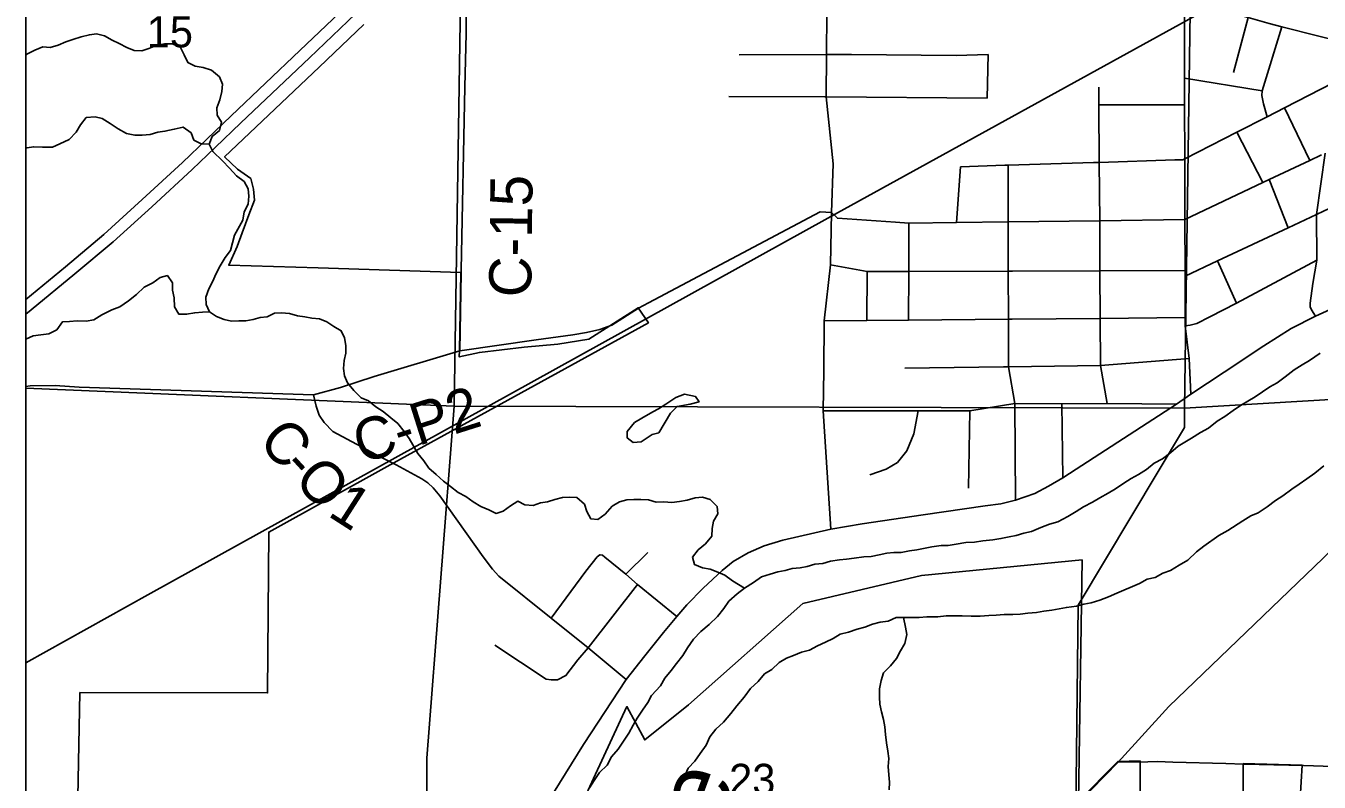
# Model space of a CAD drawing. Extents: x -6.2 to 37.4, y 0.2 to 22.2.
# Drawn here: x 1.681 to 2.552, y 16.626 to 17.135 of the extents above; entities that cross this region are included whole.
import ezdxf

# ---------------------------------------------------------------- set-up
doc = ezdxf.new("R2010")
doc.units = 0
for name, color, linetype in [('GM_X_City_Street', 7, 'Continuous'), ('GM_X_Corporation', 7, 'Continuous'), ('GM_X_County_Road', 7, 'Continuous'), ('GM_X_County_Road_Text', 7, 'Continuous'), ('GM_X_Major_River', 7, 'Continuous'), ('GM_X_Major_River_Text', 7, 'Continuous'), ('GM_X_Minor_Lake', 7, 'Continuous'), ('GM_X_Minor_River', 7, 'Continuous'), ('GM_X_Rail_Line', 7, 'Continuous'), ('GM_X_Section', 7, 'Continuous'), ('GM_X_Section_Text', 7, 'Continuous'), ('GM_X_Township_Road', 7, 'Continuous'), ('GM_X_US_Route', 7, 'Continuous'), ('GM_X_US_Shield', 7, 'Continuous'), ('SH_Cut_Line', 7, 'Continuous'), ('SH_Data', 7, 'Continuous')]:
    doc.layers.add(name, color=color, linetype=linetype)

msp = doc.modelspace()

# ---------------------------------------------------------------- linework, layer by layer
at = {"layer": 'GM_X_City_Street'}
for p, q in [((2.49427, 17.10375), (2.50408, 17.14076)), ((2.32831, 17.08654), (2.32914, 17.11596)), ((2.46132, 17.09991), (2.51363, 17.0913)), ((2.40366, 17.08196), (2.46137, 17.08188)), ((2.54559, 17.0446), (2.52864, 17.07998)), ((2.51401, 17.02959), (2.4965, 17.06358)), ((2.30763, 17.00267), (2.31032, 17.0403)), ((2.531, 16.9991), (2.51831, 17.03164)), ((2.24723, 16.93678), (2.24753, 16.96965)), ((2.49634, 16.94841), (2.48342, 16.97682)), ((2.31571, 16.82377), (2.3167, 16.87599)), ((2.3794, 16.83076), (2.37859, 16.88068)), ((2.08496, 16.76594), (2.09981, 16.78055))]:
    msp.add_line(p, q, dxfattribs=at)
for points in [[(2.22529, 17.22542), (2.28858, 17.20262), (2.31401, 17.19492), (2.34413, 17.18581), (2.37301, 17.17707), (2.37791, 17.17559), (2.40616, 17.16779), (2.43826, 17.15893), (2.46118, 17.1526), (2.50408, 17.14076), (2.51833, 17.13682), (2.52684, 17.13447), (2.60157, 17.1157)], [(2.46551, 16.88713), (2.46439, 16.91117), (2.46167, 16.93318), (2.46166, 16.93869), (2.46162, 16.96661), (2.46162, 16.97042), (2.46157, 17.00466), (2.46146, 17.0457), (2.46137, 17.08188), (2.46132, 17.09991), (2.46118, 17.1526)], [(2.51691, 17.074), (2.51444, 17.08276), (2.51334, 17.08826), (2.51363, 17.0913), (2.52684, 17.13447)], [(2.16135, 17.11568), (2.22007, 17.11581), (2.2257, 17.11582), (2.23708, 17.11585), (2.30749, 17.11515), (2.32914, 17.11596)], [(2.45766, 17.04495), (2.46015, 17.04503), (2.46146, 17.0457), (2.4965, 17.06358), (2.51691, 17.074), (2.52864, 17.07998), (2.56146, 17.09673), (2.60157, 17.1157)], [(2.40916, 16.88082), (2.40477, 16.90645), (2.40457, 16.93818), (2.40436, 16.97021), (2.40415, 17.00392), (2.4039, 17.04325), (2.40366, 17.08196), (2.40358, 17.09393)], [(2.15428, 17.08769), (2.21892, 17.08726), (2.21988, 17.08726), (2.32831, 17.08654)], [(2.46162, 16.96661), (2.48342, 16.97682), (2.531, 16.9991), (2.55019, 17.00809), (2.55499, 17.01034), (2.59535, 17.02924), (2.62986, 17.0454), (2.63854, 17.04947)], [(2.54949, 16.93963), (2.54682, 16.94398), (2.54591, 16.94601), (2.54587, 16.94847), (2.5478, 16.96164), (2.5504, 16.97728), (2.55019, 17.00809), (2.55596, 17.04954)], [(2.31032, 17.0403), (2.34019, 17.04124), (2.34242, 17.04131), (2.39992, 17.04313), (2.4039, 17.04325), (2.45467, 17.04486), (2.45766, 17.04495)], [(2.34747, 16.81584), (2.34691, 16.88096), (2.34277, 16.90564), (2.34269, 16.93763), (2.34261, 16.96999), (2.34252, 17.00312), (2.34242, 17.04131)], [(2.27548, 16.93703), (2.27551, 16.96975), (2.27554, 17.00226)], [(2.22293, 16.97418), (2.24753, 16.96965), (2.27551, 16.96975), (2.34261, 16.96999), (2.34535, 16.97), (2.40436, 16.97021), (2.46162, 16.97042)], [(2.46167, 16.93318), (2.46507, 16.93369), (2.46964, 16.93476), (2.47844, 16.93918), (2.49634, 16.94841), (2.5504, 16.97728)], [(2.21862, 16.93652), (2.24723, 16.93678), (2.27548, 16.93703), (2.34269, 16.93763), (2.34524, 16.93765), (2.40457, 16.93818), (2.46166, 16.93869)], [(2.27293, 16.90473), (2.33926, 16.90559), (2.34277, 16.90564), (2.40477, 16.90645), (2.46439, 16.91117)], [(2.218, 16.87596), (2.28178, 16.87598), (2.3167, 16.87599), (2.34691, 16.88096), (2.37859, 16.88068), (2.40916, 16.88082), (2.45584, 16.8804)], [(2.24923, 16.83276), (2.2603, 16.83658), (2.26796, 16.84121), (2.27435, 16.84908), (2.27907, 16.8604), (2.28178, 16.87598)], [(2.03476, 16.73637), (2.05812, 16.76797), (2.06569, 16.7775), (2.06751, 16.77897), (2.06926, 16.77862), (2.07094, 16.77729), (2.08496, 16.76594), (2.09288, 16.759), (2.11937, 16.73742)], [(1.99674, 16.71815), (2.03131, 16.69521), (2.03472, 16.69478), (2.03889, 16.69472), (2.04463, 16.69767), (2.05254, 16.7082), (2.05959, 16.71631), (2.09288, 16.759)]]:
    msp.add_lwpolyline(points, dxfattribs=at)
at = {"layer": 'GM_X_Corporation'}
for points in [[(1.71166, 16.39298), (1.71731, 16.68614), (1.84372, 16.68596), (1.84449, 16.79426), (1.92426, 16.83835), (2.10014, 16.9352), (2.09338, 16.94531), (2.06, 16.92423), (2.03925, 16.92078), (2.01643, 16.91869), (1.98638, 16.91521), (1.97279, 16.91224), (1.97301, 16.91657), (1.97387, 16.96913), (1.87774, 16.97218), (1.81754, 16.97393), (1.82328, 16.98658), (1.82656, 16.99577), (1.83112, 17.00781), (1.83487, 17.01774), (1.83417, 17.02524), (1.83229, 17.03226), (1.82339, 17.03859), (1.81471, 17.04695), (1.87852, 17.10733), (1.88863, 17.11704), (1.90859, 17.13599)], [(2.43124, 16.59515), (2.43138, 16.64023), (2.4164, 16.63969), (2.38997, 16.61316), (2.39224, 16.77554), (2.28405, 16.76496), (2.20418, 16.74612), (2.12725, 16.67793), (2.09773, 16.65431), (2.08576, 16.67676), (2.0646, 16.63133), (2.05451, 16.60928)], [(2.53712, 16.58129), (2.54044, 16.63725), (2.50084, 16.63835), (2.50076, 16.61249)]]:
    msp.add_lwpolyline(points, dxfattribs=at)
at = {"layer": 'GM_X_County_Road'}
msp.add_line((2.3895, 16.61161), (2.41652, 16.63941), dxfattribs=at)
for points in [[(2.22312, 16.79629), (2.218, 16.87596), (2.2184, 16.903), (2.21862, 16.93652), (2.22293, 16.97418), (2.22354, 17.00951), (2.22456, 17.04222), (2.21988, 17.08726), (2.22007, 17.11581), (2.22026, 17.14364), (2.22529, 17.22542)], [(1.97733, 17.13007), (1.9774, 17.13354), (1.97798, 17.16415)], [(1.97403, 16.97084), (1.97662, 17.09388), (1.97733, 17.13007)], [(2.26664, 17.00288), (2.27554, 17.00226), (2.30763, 17.00267), (2.34252, 17.00312), (2.40415, 17.00392), (2.46157, 17.00466), (2.51401, 17.02959), (2.51831, 17.03164), (2.54559, 17.0446), (2.55304, 17.04815), (2.55353, 17.04838)], [(2.1003, 16.94864), (2.21589, 17.01), (2.22354, 17.00951)], [(2.22354, 17.00951), (2.22751, 17.00558), (2.26664, 17.00288)], [(1.97312, 16.9163), (1.97399, 16.96885), (1.97403, 16.97084)], [(1.97312, 16.9163), (2.02448, 16.92364), (2.04919, 16.92704), (2.05851, 16.92867), (2.06753, 16.93059), (2.07564, 16.93351), (2.0935, 16.94503), (2.1003, 16.94864)], [(2.01192, 16.57962), (2.0565, 16.65126), (2.08529, 16.69502), (2.09786, 16.71098), (2.11034, 16.72661), (2.11937, 16.73742), (2.12616, 16.74524), (2.13704, 16.75661), (2.1498, 16.76832), (2.15737, 16.77442), (2.16733, 16.78038), (2.17819, 16.78493), (2.19067, 16.78879), (2.22312, 16.79629), (2.24408, 16.79979), (2.28516, 16.80596), (2.32693, 16.81185), (2.33752, 16.81339), (2.34747, 16.81584), (2.36051, 16.82026), (2.36973, 16.8251), (2.3794, 16.83076), (2.38834, 16.83666), (2.45584, 16.8804), (2.46551, 16.88713), (2.48801, 16.90185), (2.51472, 16.9198), (2.53315, 16.93129), (2.54949, 16.93963), (2.56736, 16.94784)], [(2.41652, 16.63941), (2.4508, 16.67683), (2.55476, 16.77672), (2.57495, 16.7966), (2.62938, 16.8502), (2.63598, 16.85573), (2.6496, 16.86519), (2.67762, 16.88129), (2.74084, 16.9194)], [(1.87462, 16.88665), (1.89289, 16.89161), (1.91545, 16.89908), (1.97312, 16.9163)], [(1.68086, 16.89234), (1.68385, 16.8928), (1.70059, 16.89296), (1.71687, 16.89187), (1.87462, 16.88665)], [(1.92765, 16.84086), (1.91989, 16.84464), (1.88763, 16.86209), (1.88186, 16.86801), (1.87831, 16.87304), (1.87639, 16.87896), (1.87462, 16.88665)], [(2.08529, 16.69502), (2.05959, 16.71631), (2.03476, 16.73637), (1.99933, 16.7646), (1.99519, 16.76919), (1.98883, 16.77762), (1.95968, 16.8186), (1.9551, 16.82407), (1.95169, 16.82748), (1.94755, 16.83014), (1.93024, 16.83961), (1.92765, 16.84086)]]:
    msp.add_lwpolyline(points, dxfattribs=at)
at = {"layer": 'GM_X_Major_River'}
for points in [[(2.55257, 16.91478), (2.54539, 16.90988), (2.54056, 16.90699), (2.53514, 16.90355), (2.52911, 16.8988), (2.52367, 16.89479), (2.51865, 16.8921), (2.5138, 16.88864), (2.50895, 16.88538), (2.50393, 16.88249)], [(2.50393, 16.88249), (2.49909, 16.87942), (2.49406, 16.87615), (2.48843, 16.87215), (2.4832, 16.8689), (2.47737, 16.86433), (2.47196, 16.86127), (2.46596, 16.85747), (2.45706, 16.85205), (2.45218, 16.84783), (2.44655, 16.84364), (2.44095, 16.84058), (2.43569, 16.83638), (2.43028, 16.83313), (2.42526, 16.83025), (2.42042, 16.82717), (2.41479, 16.82336), (2.40977, 16.82047), (2.40417, 16.81723), (2.39933, 16.81434), (2.39317, 16.8113), (2.38832, 16.80804), (2.38272, 16.80479), (2.37596, 16.8012), (2.37041, 16.79967), (2.36446, 16.79738), (2.35831, 16.79472), (2.35296, 16.79356), (2.34797, 16.792), (2.3432, 16.79101), (2.33766, 16.78985), (2.33214, 16.78907), (2.32547, 16.78833), (2.31976, 16.78755), (2.31405, 16.78716), (2.30738, 16.78603), (2.30204, 16.78525), (2.2973, 16.7852), (2.2912, 16.78425), (2.28089, 16.78229), (2.27613, 16.78167), (2.2704, 16.78052), (2.26547, 16.78048), (2.26071, 16.78006), (2.25555, 16.77889), (2.25021, 16.77791), (2.24526, 16.7775), (2.23879, 16.77674), (2.23364, 16.77595), (2.22889, 16.77553), (2.22279, 16.77477), (2.21762, 16.77322), (2.21229, 16.77262), (2.20712, 16.77107), (2.20235, 16.77027), (2.19702, 16.76967), (2.19224, 16.76849), (2.18747, 16.7675), (2.18211, 16.76595), (2.17635, 16.76404), (2.17093, 16.76041), (2.16493, 16.75661), (2.16006, 16.75258), (2.15441, 16.74782), (2.15102, 16.7428), (2.14668, 16.73743), (2.14101, 16.7321), (2.13555, 16.72734), (2.13064, 16.72217), (2.12647, 16.71623), (2.12327, 16.7112), (2.11912, 16.70583), (2.11555, 16.701), (2.11122, 16.69601), (2.1084, 16.69079), (2.10231, 16.68433), (2.09988, 16.67947), (2.09631, 16.67446), (2.09254, 16.66907), (2.08992, 16.66422), (2.0869, 16.6588), (2.0835, 16.65341), (2.07973, 16.64802), (2.07539, 16.64284), (2.07237, 16.63724), (2.06729, 16.63246), (2.0637, 16.62706), (2.06051, 16.62204)], [(2.12243, 16.6247), (2.12449, 16.62957), (2.12694, 16.63519), (2.13145, 16.63999), (2.13503, 16.64519), (2.139, 16.65076), (2.14165, 16.65637), (2.14561, 16.66156), (2.15069, 16.66634), (2.15561, 16.67208), (2.15976, 16.67726), (2.16469, 16.68318), (2.16886, 16.68894), (2.17413, 16.69371), (2.17827, 16.69871), (2.1833, 16.70178), (2.18819, 16.70637), (2.19321, 16.70926), (2.19802, 16.7112), (2.20321, 16.71331), (2.20876, 16.71485), (2.21397, 16.71773), (2.21936, 16.72022), (2.22456, 16.72272), (2.22939, 16.72542), (2.23494, 16.72696), (2.24069, 16.72887), (2.24605, 16.73022), (2.25104, 16.73235), (2.2562, 16.73352), (2.26173, 16.7343), (2.26712, 16.73679), (2.27206, 16.73683), (2.27698, 16.73668), (2.28248, 16.7367), (2.28781, 16.7371), (2.29502, 16.73726), (2.30073, 16.73785), (2.30586, 16.73788), (2.31155, 16.7379), (2.31761, 16.73771), (2.32368, 16.73772), (2.32958, 16.73811), (2.33452, 16.73833), (2.33984, 16.73874), (2.34572, 16.73875), (2.35066, 16.73898), (2.3558, 16.73958), (2.3617, 16.74016), (2.36647, 16.74096), (2.37181, 16.74175), (2.37676, 16.74254), (2.38173, 16.74353), (2.38859, 16.74446), (2.39356, 16.74564), (2.39833, 16.74663), (2.40426, 16.74835), (2.41003, 16.75064), (2.41561, 16.75312), (2.42042, 16.75525), (2.42619, 16.75773), (2.43099, 16.75967), (2.43621, 16.76255), (2.44155, 16.76372), (2.44658, 16.7666), (2.45194, 16.76833), (2.45775, 16.77195), (2.46355, 16.77538), (2.46941, 16.78089), (2.47428, 16.78473), (2.48437, 16.79201), (2.49055, 16.79523), (2.50062, 16.80176), (2.50585, 16.8052), (2.51085, 16.80733), (2.51686, 16.81132), (2.52249, 16.81551), (2.52752, 16.81877), (2.53354, 16.82314), (2.53859, 16.82659), (2.54363, 16.83023), (2.54907, 16.83405), (2.5551, 16.8388)]]:
    msp.add_lwpolyline(points, dxfattribs=at)
at = {"layer": 'GM_X_Minor_Lake'}
msp.add_line((2.10323, 16.8752), (2.0957, 16.87106), dxfattribs=at)
msp.add_lwpolyline([(2.0957, 16.87106), (2.09087, 16.86817), (2.08593, 16.86206), (2.08598, 16.8577), (2.08986, 16.85454), (2.09539, 16.85513), (2.10275, 16.86003), (2.10714, 16.86103), (2.11515, 16.87426), (2.11947, 16.87887), (2.12825, 16.8805), (2.13437, 16.88202), (2.13201, 16.88551), (2.12447, 16.88707), (2.11871, 16.88497), (2.11193, 16.88043), (2.1069, 16.87717), (2.10323, 16.8752)], dxfattribs=at)
at = {"layer": 'GM_X_Minor_River'}
for points in [[(1.81999, 16.98898), (1.82148, 16.99425), (1.82693, 17.00433), (1.82786, 17.00999), (1.83049, 17.01503), (1.83104, 17.02052), (1.83063, 17.02547), (1.82794, 17.03029), (1.82274, 17.03406), (1.81798, 17.03933), (1.8132, 17.04422), (1.80676, 17.05049), (1.80426, 17.05549), (1.80632, 17.06075), (1.81119, 17.06477), (1.8127, 17.07023), (1.80981, 17.07506), (1.80959, 17.08), (1.81146, 17.08526), (1.81278, 17.09091), (1.81331, 17.09583), (1.8112, 17.10082), (1.80584, 17.10535), (1.80039, 17.10704), (1.79492, 17.10796), (1.79006, 17.11039), (1.78757, 17.11559), (1.78489, 17.12098), (1.77946, 17.12305), (1.77434, 17.12301), (1.76938, 17.12222), (1.7638, 17.11992), (1.75901, 17.11836), (1.7537, 17.11852), (1.74884, 17.12057), (1.7438, 17.12319), (1.73894, 17.12561), (1.73391, 17.12843), (1.72845, 17.12973), (1.72369, 17.12912), (1.71814, 17.12777), (1.71259, 17.12604), (1.70779, 17.12429), (1.7026, 17.12217), (1.69724, 17.12063), (1.69232, 17.12097), (1.68694, 17.11886), (1.68193, 17.11635), (1.68086, 17.11568)], [(1.80426, 17.05549), (1.79895, 17.05566), (1.79411, 17.05827), (1.79217, 17.06308), (1.78679, 17.06704), (1.78086, 17.06551), (1.77456, 17.06418), (1.7698, 17.06357), (1.76463, 17.06202), (1.75911, 17.06162), (1.75418, 17.06158), (1.74871, 17.0627), (1.74312, 17.06571), (1.73774, 17.06948), (1.73234, 17.07287), (1.72744, 17.07397), (1.72154, 17.07339), (1.7176, 17.06858), (1.71478, 17.06354), (1.71007, 17.05856), (1.70372, 17.05572), (1.69872, 17.05341), (1.69208, 17.05342), (1.68621, 17.05379), (1.68144, 17.05299), (1.68086, 17.05274)], [(2.16493, 16.75661), (2.15673, 16.76142), (2.15173, 16.76536), (2.14686, 16.76722), (2.1418, 16.76927), (2.13652, 16.77019), (2.13128, 16.77244), (2.12992, 16.77742), (2.13368, 16.78223), (2.13855, 16.78626), (2.14289, 16.79163), (2.14324, 16.79674), (2.14397, 16.80165), (2.14697, 16.8065), (2.14655, 16.81144), (2.14177, 16.81614), (2.1367, 16.81782), (2.13175, 16.8174), (2.1262, 16.81586), (2.12105, 16.81488), (2.11591, 16.81428), (2.11061, 16.81463), (2.10548, 16.81441), (2.10022, 16.81589), (2.0951, 16.81624), (2.09036, 16.8162), (2.08561, 16.81596), (2.08082, 16.81459), (2.0758, 16.81171), (2.07108, 16.80635), (2.06622, 16.8027), (2.0613, 16.80323), (2.05861, 16.80806), (2.05725, 16.81303), (2.05208, 16.81756), (2.04715, 16.81771), (2.0424, 16.81747), (2.03705, 16.81612), (2.03226, 16.81475), (2.0275, 16.81394), (2.02251, 16.8122), (2.01702, 16.81256), (2.01216, 16.81498), (2.00732, 16.8119), (2.00246, 16.80826), (1.99768, 16.80688), (1.99263, 16.80932), (1.98739, 16.81156), (1.98218, 16.81457), (1.97717, 16.81833), (1.97194, 16.82095), (1.96695, 16.8249), (1.96213, 16.82865), (1.95715, 16.83298), (1.95235, 16.8373), (1.9489, 16.84215), (1.94489, 16.84721), (1.93913, 16.85725), (1.93568, 16.8621), (1.93149, 16.86735), (1.92668, 16.87129), (1.9215, 16.87544), (1.91667, 16.87862), (1.91167, 16.88257), (1.90661, 16.88462), (1.90184, 16.8897), (1.89745, 16.89477), (1.89551, 16.89957), (1.8949, 16.90433), (1.89527, 16.90983), (1.89637, 16.91473), (1.89634, 16.91985), (1.89556, 16.925), (1.89324, 16.92981), (1.88841, 16.93281), (1.88357, 16.9358), (1.8787, 16.93785), (1.87359, 16.93838), (1.86869, 16.93929), (1.86378, 16.93982), (1.85852, 16.9415), (1.85303, 16.94186), (1.84828, 16.94162), (1.84346, 16.9393), (1.8387, 16.93869), (1.83392, 16.93751), (1.82895, 16.93652), (1.82421, 16.93648), (1.81946, 16.93624), (1.81437, 16.93735), (1.80932, 16.9394), (1.80448, 16.94258), (1.80237, 16.94758), (1.80214, 16.95252), (1.80402, 16.95797), (1.80664, 16.96282), (1.8091, 16.96844), (1.81173, 16.97367), (1.81512, 16.97907), (1.81869, 16.9839), (1.81999, 16.98898)], [(1.80448, 16.94258), (1.79992, 16.94234), (1.7946, 16.94194), (1.78907, 16.94097), (1.78394, 16.94093), (1.78107, 16.94596), (1.78069, 16.95204), (1.77953, 16.9572), (1.77968, 16.96213), (1.77623, 16.96698), (1.77126, 16.9658), (1.7664, 16.96215), (1.76062, 16.9591), (1.75534, 16.95433), (1.75008, 16.94994), (1.74426, 16.94594), (1.7387, 16.94383), (1.73195, 16.94063), (1.72672, 16.93718), (1.72138, 16.9362), (1.71551, 16.93657), (1.71018, 16.93598), (1.70543, 16.93574), (1.70166, 16.93036), (1.69626, 16.92767), (1.69093, 16.92708), (1.68579, 16.92648), (1.68086, 16.9242)], [(2.27206, 16.73683), (2.27336, 16.73015), (2.27416, 16.72538), (2.27283, 16.71935), (2.27001, 16.71431), (2.26719, 16.70908), (2.26325, 16.70427), (2.25854, 16.69948), (2.25686, 16.69422), (2.25574, 16.68875), (2.25575, 16.68306), (2.25616, 16.6783), (2.25714, 16.67315), (2.25849, 16.66798), (2.25948, 16.66302), (2.25989, 16.65807), (2.26066, 16.65235), (2.26143, 16.64683), (2.26203, 16.64169), (2.26167, 16.63638), (2.26206, 16.63087), (2.26248, 16.62592), (2.26231, 16.62081)]]:
    msp.add_lwpolyline(points, dxfattribs=at)
at = {"layer": 'GM_X_Rail_Line'}
for points in [[(1.68086, 18.39138), (1.68086, 15.3872)], [(1.68086, 16.70625), (1.76291, 16.75192), (2.22097, 17.00557), (2.46431, 17.13956), (2.55096, 17.18814), (2.74322, 17.29341), (2.78445, 17.31777), (2.81399, 17.33433), (2.83834, 17.3483), (2.85977, 17.36258), (2.89872, 17.39571), (3.02565, 17.50711), (3.14192, 17.60631), (3.24354, 17.69623), (3.29532, 17.73582), (3.33196, 17.76367), (3.37104, 17.79348), (3.41794, 17.82281), (3.45898, 17.84626), (3.52017, 17.87663)]]:
    msp.add_lwpolyline(points, dxfattribs=at)
at = {"layer": 'GM_X_Section'}
for points in [[(1.97719, 17.38234), (2.46846, 17.38053), (2.46132, 16.87779), (1.96929, 16.87904)], [(2.46846, 17.38053), (2.9126, 17.3784), (2.90397, 16.89028), (2.90372, 16.88668), (2.64683, 16.88866), (2.46132, 16.87779)], [(2.46132, 16.87779), (2.64683, 16.88866), (2.90372, 16.88668), (2.89317, 16.38663), (2.89289, 16.38152), (2.38563, 16.38809), (2.38968, 16.74498), (2.46127, 16.86472)], [(1.96929, 16.87904), (2.46132, 16.87779), (2.46127, 16.86472), (2.38968, 16.74498), (2.38563, 16.38809), (1.95104, 16.39075), (1.95103, 16.64196)]]:
    msp.add_lwpolyline(points, close=True, dxfattribs=at)
at = {"layer": 'GM_X_Township_Road'}
for p, q in [((2.41652, 16.63941), (2.43652, 16.63963)), ((2.50146, 16.63806), (2.54139, 16.63702)), ((2.54139, 16.63702), (2.56136, 16.6365))]:
    msp.add_line(p, q, dxfattribs=at)
msp.add_lwpolyline([(2.43652, 16.63963), (2.44303, 16.63971), (2.45331, 16.63932), (2.48912, 16.63838), (2.50096, 16.63808), (2.50146, 16.63806)], dxfattribs=at)
at = {"layer": 'GM_X_US_Route'}
for points in [[(1.68086, 16.95097), (1.70752, 16.97299), (1.73331, 16.99459), (1.75926, 17.01813), (1.78644, 17.04312), (1.81917, 17.07454), (1.8654, 17.11846), (1.8964, 17.14807), (1.92667, 17.1771), (1.95529, 17.20416), (1.95708, 17.20587)], [(1.80831, 17.05318), (1.82558, 17.06975), (1.8718, 17.11367), (1.90281, 17.14328), (1.93307, 17.17232), (1.9617, 17.19938), (1.96206, 17.19972)], [(1.68086, 16.94107), (1.68452, 16.94391), (1.71392, 16.9682), (1.73971, 16.98981), (1.76567, 17.01335), (1.79284, 17.03833), (1.80831, 17.05318)]]:
    msp.add_lwpolyline(points, dxfattribs=at)
at = {"layer": 'GM_X_US_Shield'}
for points in [[(1.68086, 17.38941), (1.68086, 16.89117), (1.96929, 16.87904), (1.97719, 17.38234), (1.72471, 17.38725)], [(1.68086, 16.89117), (1.68086, 16.39384), (1.95104, 16.39075), (1.95103, 16.64196), (1.96929, 16.87904)]]:
    msp.add_lwpolyline(points, close=True, dxfattribs=at)
at = {"layer": 'SH_Cut_Line'}
msp.add_lwpolyline([(1.68086, 20.39726), (1.68086, 14.30742)], dxfattribs=at)
at = {"layer": 'SH_Data'}
msp.add_line((1.68086, 21.10742), (1.68086, 14.30742), dxfattribs=at)

# ---------------------------------------------------------------- texts
at = {"layer": 'GM_X_County_Road_Text'}
for s, height, rotation, p in [('C-15', 0.028409, 89.31291, (2.02121, 16.95229)), ('C-P2', 0.028409, 17.60877, (1.90688, 16.84003)), ('C', 0.02841, 312.42965, (1.83646, 16.85482)), ('-', 0.02841, 312.56694, (1.85225, 16.83754)), ('O', 0.02841, 313.41443, (1.86046, 16.82861)), ('1', 0.02841, 327.31746, (1.88342, 16.80566))]:
    msp.add_text(s, height=height, rotation=rotation, dxfattribs=at).set_placement(p)
at = {"layer": 'GM_X_Major_River_Text'}
msp.add_text('Maumee', height=0.047383, rotation=69.77352, dxfattribs=at).set_placement((2.07377, 16.39663))
at = {"layer": 'GM_X_Section_Text'}
for s, p in [('15', (1.76228, 17.12067)), ('23', (2.15457, 16.61729))]:
    msp.add_text(s, height=0.020928, rotation=0.00001, dxfattribs=at).set_placement(p)

doc.saveas('drawing.dxf')
